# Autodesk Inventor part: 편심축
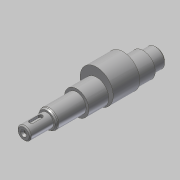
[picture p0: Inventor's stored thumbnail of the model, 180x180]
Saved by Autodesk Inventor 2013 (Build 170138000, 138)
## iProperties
Created: 2019-01
Part Number: 편심축
Material: 강철, 연강
Document SubType Name: Modeling
Designer: mduedu
Density: 1 g/cm^3
Author: mduedu
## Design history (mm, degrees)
sketch "스케치1"
  geometry: L1 (0, 0)-(21, 0); L2 (21, 0)-(21, 6); L3 (21, 6)-(0, 6); L4 (0, 6)-(0, 0); L5 (21, 0)-(48, 0); L6 (48, 0)-(48, 8.5); L7 (48, 8.5)-(21, 8.5); L8 (21, 8.5)-(21, 0); L9 (48, 0)-(108, 0); L10 (108, 0)-(108, 11); L11 (108, 11)-(48, 11); L12 (48, 11)-(48, 0); L13 (108, 0)-(120, 0); L14 (120, 0)-(120, 8.5); L15 (120, 8.5)-(108, 8.5); L16 (108, 8.5)-(108, 0)
  constraints: 32 end point, 8 parallel, 4 horizontal, 4 perpendicular
  dimensions: "d0" = 120 distance between parallel lines of L14 L4; "d2" = 12 distance of L14.end L15.end; "d3" = 60 distance of L10.end L11.end; "d4" = 99 distance between parallel lines of L8 L14; "d5" = 12 diameter of L3 L1; "d6" = 17 diameter of L7 L5; "d7" = 17 diameter of L15 L13; "d8" = 22 diameter of L11 L9
revolve "회전1" sketch "스케치1" stored, may be unused: angle "d9" = 90 deg
node "작업 평면1"
sketch "스케치2"
  geometry: C1 r 15 at (0, 4); C2 r 11 at (0, 0) reference; 1 further point
  constraints: 1 centre point, 1 tangent, 1 vertical alignment
  dimensions: "d11" = 4 distance of point (0, 0) C1.centre
extrude "돌출1" join sketch "스케치2" distance "d12" = 24; taper "d13" = 0 deg
node "작업 평면2"
sketch "스케치3" dims "d16" = 12
  geometry: L1 (-4.5, 2)-(3.5, 2); L2 (3.5, 2)-(3.5, -2); L3 (3.5, -2)-(-4.5, -2); L4 (-4.5, -2)-(-4.5, 2); L5 (-10.5, 8.5)-(-10.5, -8.5) reference; 3 further points
  constraints: 8 end point, 2 midpoint, 2 parallel, 2 vertical alignment, 1 horizontal, 1 horizontal alignment, 1 perpendicular, 4 other
  dimensions: "d14" = 4 distance between parallel lines of L3 L1; "d17" = 4 dimension on L5
extrude "돌출2" cut sketch "스케치3" distance "d18" = 2.5; taper "d19" = 0 deg
chamfer "모따기1" distance "d20" = 1.82; stored, may be unused: second distance "d21" = 2, angle "d22" = 30 deg
fillet "모깎기1" dims "d23" = 2
hole "구멍2" diameter "d39" = 3.242; stored, may be unused: countersink angle "d43" = 60 deg, drill point angle "d45" = 118 deg; dims "d37" = 10, "d38" = 10, "d40" = 8, "d41" = 5.51, "d42" = 2, "d44" = 10
sketch "스케치5"
  geometry: L1 (0, 0)-(2, 0); L2 (2, 0)-(2, 1.621); L3 (0, 2.776)-(0, 0); L4 (0, 2.776)-(2, 1.621); L5 (10, 1.621)-(0, 1.621) reference
  constraints: 8 end point, 1 horizontal, 1 parallel, 1 perpendicular, 1 point on line
  dimensions: "d46" = 2 distance between parallel lines of L2 L3; "d48" = 30 deg angle of L4 L1
revolve "회전2" sketch "스케치5" stored, may be unused: angle "d50" = 90 deg
chamfer "모따기2" distance "d25" = 1; stored, may be unused: second distance "d26" = 2, angle "d27" = 30 deg
node "솔리드1"
